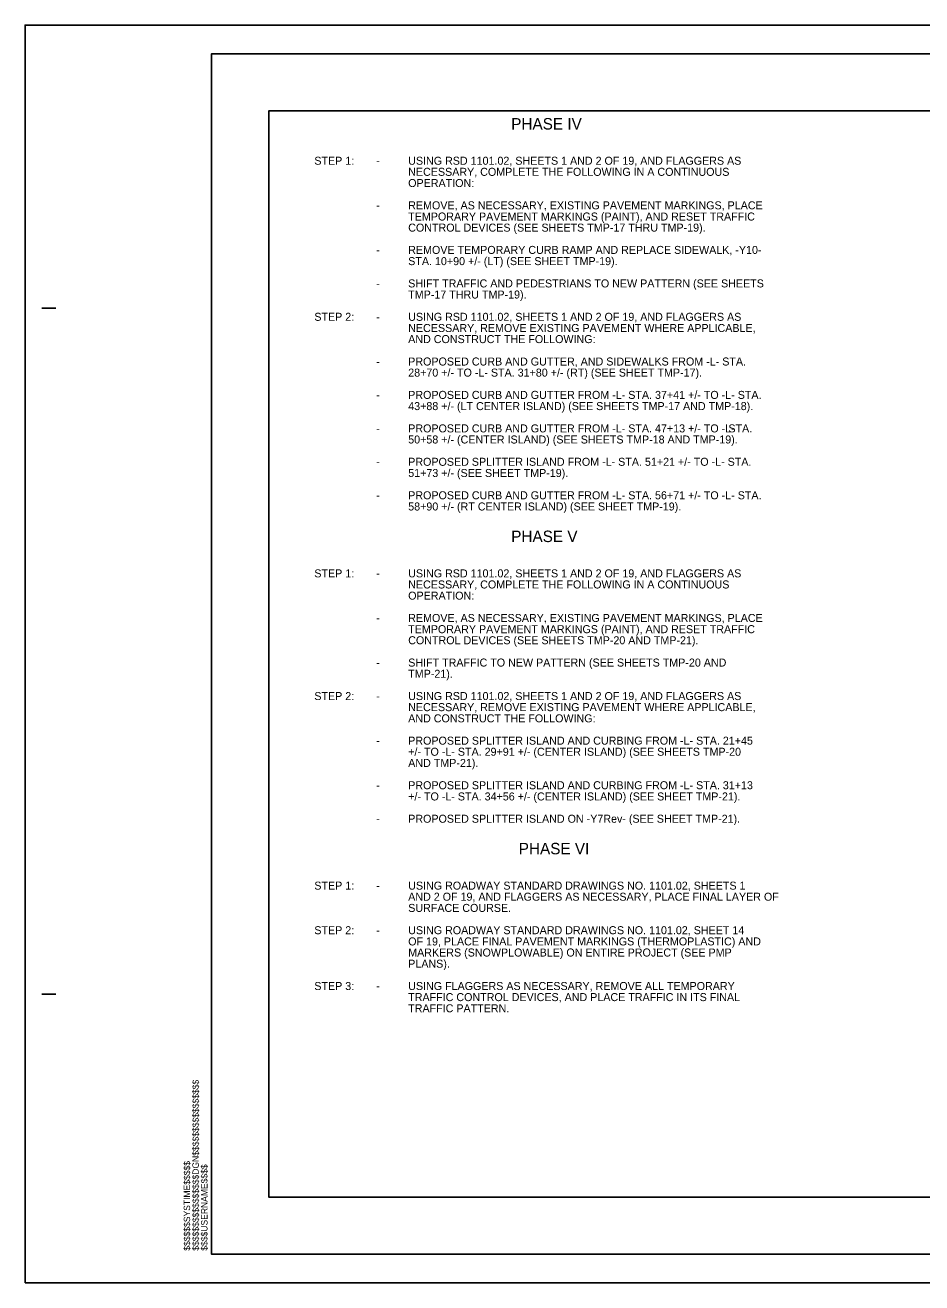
# Model space of a CAD drawing. Extents: x 764226 to 769781, y 650021 to 652521.
# Drawn here: x 766449 to 767233, y 650021 to 651121 of the extents above; entities that cross this region are included whole.
import ezdxf

# ---------------------------------------------------------------- set-up
doc = ezdxf.new("R2010")
doc.units = 0
for name, color, linetype in [('Default', 7, 'Continuous'), ('DEV BORDER CELL', 7, 'Continuous'), ('Scratch_Level_0', 7, 'Continuous'), ('Sheet Plot Border Outside CELL', 7, 'Continuous')]:
    doc.layers.add(name, color=color, linetype=linetype)

msp = doc.modelspace()

# ---------------------------------------------------------------- linework, layer by layer
at = {"layer": 'DEV BORDER CELL'}
for p, q in [((766613.3, 651096.1), (766613.3, 651096.1)), ((766463.8, 650873.6), (766476.3, 650873.6)), ((766463.8, 650273.6), (766476.3, 650273.6)), ((766612.3, 650046.1), (766612.3, 650046.1))]:
    msp.add_line(p, q, dxfattribs=at)
msp.add_lwpolyline([(768112.3, 651096.1), (766612.3, 651096.1), (766612.3, 650046.1), (768112.3, 650046.1)], close=True, dxfattribs=at)
at = {"layer": 'Scratch_Level_0'}
msp.add_lwpolyline([(768062.3, 651046.1), (766662.3, 651046.1), (766662.3, 650096.1), (767541.2, 650096.1), (767541.2, 650214.4), (768062.3, 650214.4)], close=True, dxfattribs=at)
at = {"layer": 'Sheet Plot Border Outside CELL'}
msp.add_lwpolyline([(766449.3, 650021.1), (768137.3, 650021.1), (768137.3, 651121.1), (766449.3, 651121.1)], close=True, dxfattribs=at)

# ---------------------------------------------------------------- texts
at = {"layer": 'Default'}
for s, height, p in [('PHASE IV', 10, (766874.4, 651029.8)), ('STEP 1:', 7, (766702.2, 650999)), ('-', 7, (766756.3, 650999)), ('USING RSD 1101.02, SHEETS 1 AND 2 OF 19, AND FLAGGERS AS ', 7, (766784.3, 650999)), ('NECESSARY, COMPLETE THE FOLLOWING IN A CONTINUOUS ', 7, (766784.3, 650989.3)), ('OPERATION:', 7, (766784.3, 650979.5)), ('-', 7, (766756.3, 650960)), ('REMOVE, AS NECESSARY, EXISTING PAVEMENT MARKINGS, PLACE ', 7, (766784.3, 650960)), ('TEMPORARY PAVEMENT MARKINGS (PAINT), AND RESET TRAFFIC ', 7, (766784.3, 650950.2)), ('CONTROL DEVICES (SEE SHEETS TMP-17 THRU TMP-19).', 7, (766784.3, 650940.5)), ('REMOVE TEMPORARY CURB RAMP AND REPLACE SIDEWALK, -Y10- ', 7, (766784.3, 650921)), ('-', 7, (766756.3, 650921)), ('STA. 10+90 +/- (LT) (SEE SHEET TMP-19).', 7, (766784.3, 650911.2)), ('-', 7, (766756.3, 650891.7)), ('SHIFT TRAFFIC AND PEDESTRIANS TO NEW PATTERN (SEE SHEETS ', 7, (766784.3, 650891.7)), ('TMP-17 THRU TMP-19).', 7, (766784.3, 650882)), ('STEP 2:', 7, (766702.2, 650862.5)), ('-', 7, (766756.3, 650862.5)), ('USING RSD 1101.02, SHEETS 1 AND 2 OF 19, AND FLAGGERS AS ', 7, (766784.3, 650862.5)), ('NECESSARY, REMOVE EXISTING PAVEMENT WHERE APPLICABLE, ', 7, (766784.3, 650852.7)), ('AND CONSTRUCT THE FOLLOWING:', 7, (766784.3, 650843)), ('-', 7, (766756.3, 650823.4)), ('PROPOSED CURB AND GUTTER, AND SIDEWALKS FROM -L- STA. ', 7, (766784.3, 650823.4)), ('28+70 +/- TO -L- STA. 31+80 +/- (RT) (SEE SHEET TMP-17). ', 7, (766784.3, 650813.7)), ('-', 7, (766756.3, 650794.2)), ('PROPOSED CURB AND GUTTER FROM -L- STA. 37+41 +/- TO -L- STA. ', 7, (766784.3, 650794.2)), ('43+88 +/- (LT CENTER ISLAND) (SEE SHEETS TMP-17 AND TMP-18).', 7, (766784.3, 650784.4)), ('PROPOSED CURB AND GUTTER FROM -L- STA. 47+13 +/- TO -L-', 7, (766784.3, 650764.9)), ('STA. ', 7, (767064.3, 650764.9)), ('-', 7, (766756.3, 650764.9)), ('50+58 +/- (CENTER ISLAND) (SEE SHEETS TMP-18 AND TMP-19).', 7, (766784.3, 650755.2)), ('-', 7, (766756.3, 650735.7)), ('PROPOSED SPLITTER ISLAND FROM -L- STA. 51+21 +/- TO -L- STA. ', 7, (766784.3, 650735.7)), ('51+73 +/- (SEE SHEET TMP-19).', 7, (766784.3, 650725.9)), ('-', 7, (766756.3, 650706.4)), ('PROPOSED CURB AND GUTTER FROM -L- STA. 56+71 +/- TO -L- STA. ', 7, (766784.3, 650706.4)), ('58+90 +/- (RT CENTER ISLAND) (SEE SHEET TMP-19).', 7, (766784.3, 650696.6)), ('PHASE V', 10, (766874.4, 650669)), ('STEP 1:', 7, (766702.2, 650638.1)), ('-', 7, (766756.3, 650638.1)), ('USING RSD 1101.02, SHEETS 1 AND 2 OF 19, AND FLAGGERS AS ', 7, (766784.3, 650638.1)), ('NECESSARY, COMPLETE THE FOLLOWING IN A CONTINUOUS ', 7, (766784.3, 650628.4)), ('OPERATION:', 7, (766784.3, 650618.6)), ('REMOVE, AS NECESSARY, EXISTING PAVEMENT MARKINGS, PLACE ', 7, (766784.3, 650599.1)), ('-', 7, (766756.3, 650599.1)), ('TEMPORARY PAVEMENT MARKINGS (PAINT), AND RESET TRAFFIC ', 7, (766784.3, 650589.3)), ('CONTROL DEVICES (SEE SHEETS TMP-20 AND TMP-21).', 7, (766784.3, 650579.6)), ('-', 7, (766756.3, 650560.1)), ('SHIFT TRAFFIC TO NEW PATTERN (SEE SHEETS TMP-20 AND ', 7, (766784.3, 650560.1)), ('TMP-21).', 7, (766784.3, 650550.3)), ('STEP 2:', 7, (766702.2, 650530.8)), ('-', 7, (766756.3, 650530.8)), ('USING RSD 1101.02, SHEETS 1 AND 2 OF 19, AND FLAGGERS AS ', 7, (766784.3, 650530.8)), ('AND CONSTRUCT THE FOLLOWING:', 7, (766784.3, 650511.3)), ('NECESSARY, REMOVE EXISTING PAVEMENT WHERE APPLICABLE, ', 7, (766784.3, 650521.1)), ('PROPOSED SPLITTER ISLAND AND CURBING FROM -L- STA. 21+45 ', 7, (766784.3, 650491.8)), ('-', 7, (766756.3, 650491.8)), ('+/- TO -L- STA. 29+91 +/- (CENTER ISLAND) (SEE SHEETS TMP-20 ', 7, (766784.3, 650482.1)), ('AND TMP-21).', 7, (766784.3, 650472.3)), ('-', 7, (766756.3, 650452.8)), ('PROPOSED SPLITTER ISLAND AND CURBING FROM -L- STA. 31+13 ', 7, (766784.3, 650452.8)), ('+/- TO -L- STA. 34+56 +/- (CENTER ISLAND) (SEE SHEET TMP-21).', 7, (766784.3, 650443)), ('PROPOSED SPLITTER ISLAND ON -Y7Rev- (SEE SHEET TMP-21).', 7, (766784.3, 650423.5)), ('-', 7, (766756.3, 650423.5)), ('PHASE VI', 10, (766881, 650395.9)), ('STEP 1:', 7, (766702.2, 650365)), ('-', 7, (766756.3, 650365)), ('USING ROADWAY STANDARD DRAWINGS NO. 1101.02, SHEETS 1 ', 7, (766784.3, 650365)), ('AND 2 OF 19, AND FLAGGERS AS NECESSARY, PLACE FINAL LAYER OF ', 7, (766784.3, 650355.3)), ('SURFACE COURSE.', 7, (766784.3, 650345.5)), ('STEP 2:', 7, (766702.2, 650326)), ('USING ROADWAY STANDARD DRAWINGS NO. 1101.02, SHEET 14 ', 7, (766784.3, 650326)), ('-', 7, (766756.3, 650326)), ('OF 19, PLACE FINAL PAVEMENT MARKINGS (THERMOPLASTIC) AND ', 7, (766784.3, 650316.2)), ('MARKERS (SNOWPLOWABLE) ON ENTIRE PROJECT (SEE PMP ', 7, (766784.3, 650306.5)), ('PLANS).', 7, (766784.3, 650296.7)), ('STEP 3:', 7, (766702.2, 650277.2)), ('-', 7, (766756.3, 650277.2)), ('USING FLAGGERS AS NECESSARY, REMOVE ALL TEMPORARY ', 7, (766784.3, 650277.2)), ('TRAFFIC CONTROL DEVICES, AND PLACE TRAFFIC IN ITS FINAL ', 7, (766784.3, 650267.5)), ('TRAFFIC PATTERN.', 7, (766784.3, 650257.7))]:
    msp.add_text(s, height=height, rotation=359.9999, dxfattribs=at).set_placement(p)
at = {"layer": 'DEV BORDER CELL'}
for s, p in [('$$$$$$$$$$$$$$$$DGN$$$$$$$$$$$$$$$$', (766601.2, 650049.2)), ('$$$$$$SYSTIME$$$$$', (766593.6, 650049.2)), ('$$$$USERNAME$$$$', (766608.8, 650049.2))]:
    msp.add_text(s, height=5.584, rotation=90, dxfattribs=at).set_placement(p)

doc.saveas('drawing.dxf')
